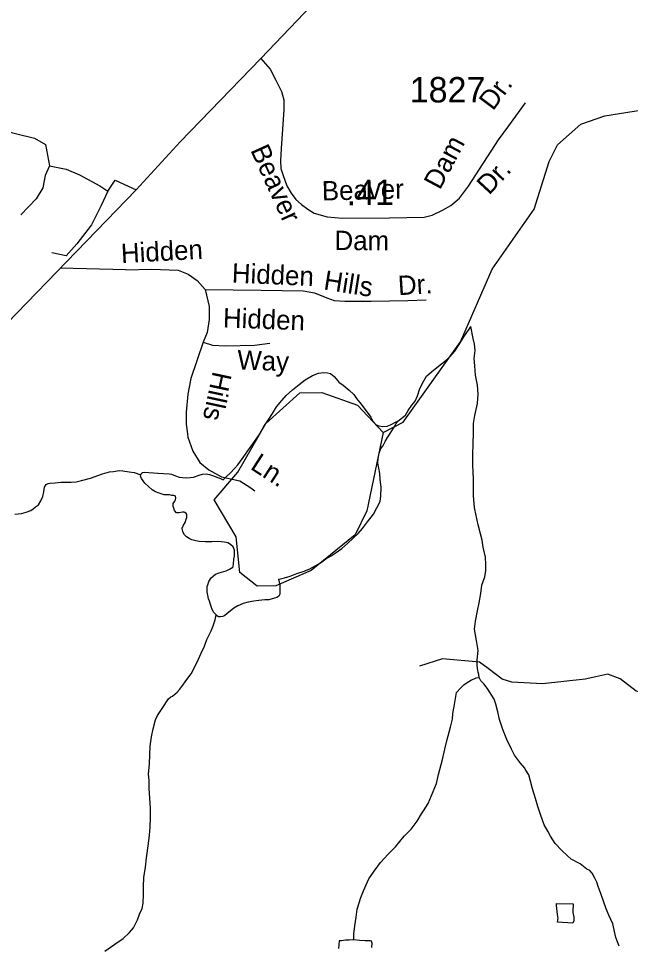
# Model space of a CAD drawing. Extents: x 2126262 to 2293712, y 749403 to 919119.
# Drawn here: x 2184249 to 2187256, y 811845 to 816398 of the extents above; entities that cross this region are included whole.
import ezdxf

# ---------------------------------------------------------------- set-up
doc = ezdxf.new("R2010")
doc.units = 0
for name, color, linetype in [('Exist Hydrographic Creek Single Shore', 7, 'Continuous'), ('Exist Hydrographic Misc Water Feature', 7, 'Continuous'), ('Exist Hydrographic Pond Under 1500 Sq Ft', 7, 'Continuous'), ('Exist Road Non-System Type 51', 7, 'Continuous'), ('Exist Road Non-System Type 51 Label', 7, 'Continuous'), ('Exist Road Primary US Attributed', 7, 'Continuous'), ('Exist Road Secondary Mileage Hundredths English Label', 7, 'Continuous'), ('Exist Road Secondary Type 51 Attributed', 7, 'Continuous'), ('Exist Road Secondary Type 51 Label', 7, 'Continuous'), ('Exist Road Secondary Type 51 Number Label', 7, 'Continuous')]:
    doc.layers.add(name, color=color, linetype=linetype)

msp = doc.modelspace()

# ---------------------------------------------------------------- linework, layer by layer
at = {"layer": 'Exist Hydrographic Creek Single Shore'}
msp.add_lwpolyline([(2186040.7, 814364.5), (2186139.7, 814414.9), (2186420.6, 814809.3), (2186576.7, 815167), (2186782.8, 815461.3), (2186855.8, 815695.9), (2186896.8, 815777.1), (2187012.6, 815879.7), (2187129.7, 815919.9), (2187345.6, 815954.8)], dxfattribs=at)
at = {"layer": 'Exist Hydrographic Misc Water Feature'}
for points in [[(2186112.5, 814420.1), (2186150.3, 814450.4), (2186164, 814472.5), (2186182.1, 814498.6), (2186197.9, 814518.7), (2186209.5, 814544.7), (2186221.2, 814580.8), (2186241.1, 814619), (2186253, 814641), (2186278.8, 814663.2), (2186296.9, 814677.3), (2186326.6, 814701.6), (2186350.4, 814719.7), (2186370.3, 814737.8), (2186392, 814763.9), (2186413.8, 814796.1), (2186437.6, 814834.2), (2186463.4, 814872.4), (2186471.4, 814884.4)], [(2186513, 813161.3), (2186511, 813175.2), (2186506.9, 813187.2), (2186504.8, 813207.2), (2186502.6, 813221.1), (2186502.6, 813247.1), (2186508.1, 813293.2), (2186499.9, 813343.1), (2186489.2, 813399), (2186495, 813437), (2186504.8, 813489.1), (2186512.6, 813527.1), (2186520.4, 813573.2), (2186526.1, 813615.2), (2186539.5, 813655.3), (2186545.6, 813687.3), (2186545.4, 813715.4), (2186543.2, 813751.3), (2186532.5, 813801.2), (2186526.3, 813835.2), (2186518.3, 813867.1), (2186507.9, 813911), (2186497.6, 813956.9), (2186489.2, 813996.8), (2186485.1, 814052.8), (2186484.5, 814102.8), (2186484.3, 814138.8), (2186481.8, 814202.7), (2186481.6, 814254.7), (2186483.1, 814310.7), (2186484.7, 814360.7), (2186484.5, 814408.6), (2186490.3, 814448.7), (2186503.8, 814506.8), (2186507.5, 814552.8), (2186503.4, 814596.7), (2186494.8, 814646.7), (2186490.7, 814692.7), (2186488.4, 814728.6), (2186492.1, 814766.6), (2186489.8, 814798.6), (2186483.5, 814826.5), (2186471.4, 814884.4)], [(2185254.8, 814132.3), (2185268.6, 814146.4), (2185288.6, 814164.5), (2185312.2, 814188.7), (2185326.4, 814204.8), (2185352, 814241), (2185375.8, 814275.1), (2185399.6, 814309.3), (2185427.3, 814347.4), (2185454.7, 814393.6), (2185478.5, 814429.8), (2185496.6, 814457.9), (2185516.3, 814490), (2185542.1, 814522.1), (2185563.8, 814546.3), (2185595.6, 814574.5), (2185627.6, 814600.7), (2185657.3, 814622.9), (2185693, 814645.2), (2185723.2, 814655.4), (2185749, 814659.5), (2185767, 814657.7), (2185781, 814653.8), (2185799, 814639.9), (2185809.3, 814628), (2185823.2, 814612.1), (2185843.3, 814596.2), (2185873.7, 814572.4), (2185895.8, 814550.6), (2185909.8, 814530.7), (2185930.1, 814504.9), (2185956.3, 814471), (2185980.5, 814439.2), (2185990.5, 814419.3), (2186006.7, 814401.4), (2186018.8, 814397.5), (2186036.9, 814393.6), (2186060.9, 814395.8), (2186076.7, 814401.9), (2186104.6, 814416.1), (2186112.5, 814420.1)], [(2185526.1, 813644.3), (2185530, 813644.3), (2185556, 813650.5), (2185584.1, 813658.7), (2185615.9, 813671), (2185651.8, 813683.2), (2185679.5, 813695.3), (2185709.6, 813711.6), (2185737.3, 813727.8), (2185759.2, 813743.9), (2185785.3, 813758.1), (2185809.1, 813774.2), (2185836.8, 813794.4), (2185866.9, 813820.6), (2185892.5, 813844.7), (2185918.4, 813868.9), (2185938.3, 813893.1), (2185964.1, 813925.3), (2185993.8, 813963.5), (2186025.4, 814025.7), (2186029.1, 814053.6), (2186030.7, 814093.6), (2186026.6, 814135.6), (2186024.4, 814163.6), (2186020.1, 814189.5), (2186014.1, 814213.5), (2186015.8, 814237.5), (2186021.5, 814263.5), (2186029.5, 814285.6), (2186039.3, 814297.7), (2186051.2, 814319.7), (2186061.1, 814339.8), (2186075, 814359.9), (2186090.8, 814386), (2186104.6, 814408.1), (2186112.5, 814420.1)], [(2184231, 813962.8), (2184263, 813967), (2184286.8, 813973.2), (2184308.9, 813981.2), (2184320.8, 813989.3), (2184332.9, 813999.4), (2184346.6, 814009.5), (2184358.5, 814029.5), (2184368.6, 814049.5), (2184372.3, 814073.6), (2184376.4, 814095.6), (2184384.2, 814109.6), (2184394, 814113.6), (2184402, 814115.7), (2184428, 814117.8), (2184458, 814120), (2184488.1, 814120.2), (2184508, 814120.3), (2184532, 814122.4), (2184558, 814128.6), (2184601.7, 814140.8), (2184661.8, 814161.1), (2184695.6, 814171.3), (2184715.5, 814173.4), (2184743.6, 814177.6), (2184761.5, 814175.7), (2184791.6, 814171.9), (2184817.6, 814168), (2184849.8, 814156.2)], [(2184849.8, 814156.2), (2184851.5, 814162.2), (2184857.6, 814168.3), (2184867.5, 814170.3), (2184933.5, 814164.6), (2184989.5, 814160.9)], [(2184989.5, 814160.9), (2184999.7, 814159.1), (2185019.8, 814151.2), (2185038.1, 814145.3), (2185054.1, 814143.4), (2185076.2, 814141.4), (2185108.6, 814145.4), (2185136.5, 814155.5), (2185152.5, 814159.6), (2185170.5, 814161.7), (2185186.5, 814157.8), (2185202.5, 814154), (2185240.9, 814138.2), (2185254.8, 814132.3)], [(2184990.3, 814059), (2184980.3, 814059), (2184964.3, 814058.9), (2184940.1, 814066.7), (2184922, 814072.7), (2184906, 814082.5), (2184869.7, 814116.3), (2184853.7, 814138.2), (2184847.8, 814150.2), (2184849.8, 814156.2)], [(2185219.3, 813468.3), (2185207.2, 813482.2), (2185199, 813500.2), (2185193.1, 813514), (2185186.7, 813536), (2185182.8, 813548), (2185178.7, 813565.9), (2185176.5, 813582), (2185176.5, 813596), (2185176.3, 813608), (2185178.3, 813616), (2185184.3, 813632), (2185196, 813650.1), (2185216.1, 813668.2), (2185234.1, 813674.3), (2185269.8, 813684.6), (2185285.8, 813692.7), (2185301.8, 813702.7), (2185303.8, 813706.7), (2185305.5, 813718.7), (2185307.5, 813742.8), (2185309.4, 813758.8), (2185309.2, 813786.8), (2185303, 813802.8), (2185291.1, 813814.7), (2185276.8, 813822.6), (2185260.8, 813826.4), (2185228.8, 813828.2), (2185198.8, 813828), (2185166.8, 813827.8), (2185136.9, 813829.6), (2185120.7, 813831.5), (2185100.8, 813837.3), (2185086.9, 813843.3), (2185074.8, 813851.2), (2185064.7, 813861.1), (2185056.5, 813877), (2185054.5, 813887), (2185052.6, 813895), (2185060.2, 813909), (2185068.2, 813923.1), (2185072.1, 813939.2), (2185076, 813947.2), (2185075.8, 813955.2), (2185075.8, 813961.2), (2185071.9, 813967.2), (2185065.8, 813971.2), (2185061.9, 813973.2), (2185053.9, 813973.2), (2185037.9, 813969), (2185031.7, 813969), (2185025.8, 813969), (2185015.3, 813981), (2185011.2, 813993), (2185009.2, 814001), (2185009.2, 814009), (2185008.8, 814015.1), (2185016.5, 814027.1), (2185020.6, 814033.1), (2185022.5, 814043.2), (2185020.2, 814049.1), (2185018.4, 814053.2), (2185012.2, 814055.1), (2185002.4, 814055.1), (2184990.3, 814059)], [(2185526.1, 813644.3), (2185532.3, 813614.4), (2185532.3, 813592.4), (2185532.7, 813570.4), (2185528.6, 813560.4), (2185518.5, 813554.3), (2185506.8, 813550.2), (2185478.7, 813542), (2185458.8, 813541.9), (2185428.9, 813539.7), (2185404.7, 813535.5), (2185376.8, 813531.3), (2185352.8, 813525.1), (2185327, 813513), (2185307.1, 813500.9), (2185289.3, 813486.8), (2185273.3, 813474.6), (2185261.4, 813464.6), (2185251.3, 813460.5), (2185241.3, 813458.4), (2185231.2, 813458.3), (2185223.2, 813464.3), (2185219.3, 813468.3)], [(2184997.9, 813065.4), (2185005.5, 813069.4), (2185027.6, 813089.5), (2185041.4, 813103.6), (2185055.5, 813123.6), (2185067.4, 813139.6), (2185081.3, 813157.5), (2185097.3, 813179.6), (2185113.1, 813209.6), (2185132.8, 813251.7), (2185146.5, 813279.8), (2185162.5, 813314), (2185174.2, 813348), (2185195.8, 813390.1), (2185205.8, 813414.2), (2185215.7, 813444.3), (2185219.3, 813468.3)], [(2185896, 811871.4), (2185895.8, 811899.4), (2185901.6, 811941.4), (2185907.3, 811983.4), (2185913, 812023.5), (2185930.5, 812079.6), (2185944.2, 812113.7), (2185970, 812171.8), (2185995.9, 812210), (2186027.5, 812252.2), (2186065, 812292.5), (2186100.9, 812328.7), (2186144.5, 812380.9), (2186178.4, 812415.2), (2186208.1, 812455.4), (2186229.8, 812491.5), (2186239.5, 812505.6), (2186261.2, 812541.7), (2186302.8, 812640), (2186312.3, 812684), (2186331.7, 812758.1), (2186343.6, 812808.2), (2186355.3, 812856.2), (2186370.7, 812916.3), (2186380.6, 812956.4), (2186382.4, 812984.4), (2186390, 813018.4), (2186395.7, 813058.5), (2186401.5, 813086.5), (2186421.6, 813110.7), (2186437.4, 813124.8), (2186449.2, 813132.8), (2186461.3, 813140.9), (2186475.1, 813149), (2186487, 813155.1), (2186497, 813159.2), (2186513, 813161.3)], [(2187199.7, 811840.4), (2187183.5, 811884.2), (2187169, 811950.1), (2187148.9, 811994), (2187136.6, 812023.9), (2187112.4, 812095.7), (2187097.8, 812133.6), (2187089.8, 812155.5), (2187081.6, 812175.4), (2187067.5, 812199.4), (2187055.4, 812213.3), (2187041.2, 812219.2), (2187009.2, 812244.9), (2186965.2, 812268.6), (2186947.1, 812284.5), (2186918.8, 812310.3), (2186886.6, 812346.1), (2186862.2, 812381.9), (2186850.1, 812405.8), (2186831.9, 812437.6), (2186813.6, 812487.5), (2186801.3, 812527.4), (2186789, 812567.3), (2186774.9, 812613.2), (2186764.6, 812651.1), (2186756.2, 812683.1), (2186738, 812711), (2186736.1, 812715), (2186715.8, 812740.7), (2186685.5, 812778.6), (2186671.3, 812808.5), (2186649, 812856.2), (2186628.9, 812906.1), (2186612.5, 812954), (2186604.3, 812991.9), (2186594, 813029.8), (2186585.8, 813053.8), (2186555.5, 813103.6), (2186537.2, 813127.5), (2186521, 813145.3), (2186513, 813161.3)], [(2184672.9, 811815.9), (2184722.5, 811850.2), (2184762.5, 811878.4), (2184794.3, 811908.6), (2184814, 811930.7), (2184833.8, 811970.8), (2184843.9, 811998.8), (2184855.6, 812026.9), (2184861.5, 812052.9), (2184863.4, 812094.9), (2184863, 812134.9), (2184864.8, 812178.9), (2184872.6, 812228.9), (2184878.3, 812274.9), (2184887.8, 812345), (2184891.5, 812387), (2184895.4, 812425), (2184897, 812473), (2184896.8, 812519), (2184894.5, 812568.9), (2184890.2, 812614.8), (2184890, 812652.9), (2184887.8, 812686.9), (2184891.5, 812734.9), (2184893.3, 812782.9), (2184895.2, 812822.9), (2184902.7, 812868.9), (2184910.5, 812908.9), (2184922.2, 812953), (2184932.3, 812975), (2184954, 813009.1), (2184985.8, 813055.3), (2184997.9, 813065.4)], [(2186973.4, 811954.7), (2186897.3, 811958.3), (2186901, 811976.3), (2186897.1, 811996.3), (2186894.8, 812026.2), (2186892.6, 812040.2), (2186892.6, 812046.2), (2186892.6, 812050.2), (2186974.6, 812048.7), (2186974.6, 812038.8), (2186972.7, 812020.8), (2186972.7, 812006.8), (2186977, 811982.8), (2186977, 811972.8), (2186977, 811964.8), (2186973.4, 811954.7)], [(2185896, 811871.4), (2185892.1, 811871.4), (2185874.1, 811871.2), (2185856, 811871.1), (2185836.1, 811867), (2185824, 811866.9), (2185822.4, 811846.9), (2185820.3, 811828.9)], [(2185984.4, 811834), (2185986.2, 811856), (2185984, 811866), (2185978, 811867.9), (2185952, 811867.8), (2185924.1, 811869.6), (2185896, 811871.4)]]:
    msp.add_lwpolyline(points, dxfattribs=at)
at = {"layer": 'Exist Hydrographic Pond Under 1500 Sq Ft'}
msp.add_lwpolyline([(2186040.7, 814364.5), (2185959.7, 813979), (2185902.7, 813862.1), (2185686.7, 813686.1), (2185512.6, 813611), (2185420.6, 813609.5), (2185336.7, 813676.9), (2185318.7, 813851.2), (2185209.6, 814033.9), (2185325.6, 814169.2), (2185464.7, 814409.2), (2185630.8, 814559.9), (2185738.6, 814560.9), (2185914.8, 814498.3), (2186040.7, 814364.5)], dxfattribs=at)
at = {"layer": 'Exist Road Non-System Type 51'}
for points in [[(2183871.3, 815933.2), (2183935.9, 815898.7), (2184152.2, 815852.6), (2184326.6, 815810.8), (2184381.7, 815779.3), (2184401.3, 815674.6)], [(2184401.3, 815674.6), (2184378.9, 815627.1), (2184367.8, 815565.7), (2184335, 815511.9), (2184259.6, 815433.7)], [(2184401.3, 815674.6), (2184482.9, 815658.5), (2184548.5, 815630.6), (2184647.5, 815576.1), (2184688, 815549.6)], [(2184688, 815549.6), (2184724.3, 815604.1), (2184826.3, 815557.2)], [(2184688, 815549.6), (2184654.5, 815479.8), (2184607.1, 815384.8), (2184534.5, 815291.3), (2184482.9, 815232.6), (2184413.1, 815246.9)], [(2184775.3, 815164.2), (2184453.1, 815171.6)], [(2184775.3, 815164.2), (2184902.8, 815166.4), (2185032.5, 815162), (2185083, 815142.2), (2185127, 815111.4), (2185166.5, 815067.4)], [(2185166.5, 815067.4), (2185186.3, 814983.8), (2185186.3, 814920.1), (2185175.3, 814856.3), (2185155.6, 814807.9)], [(2185166.5, 815067.4), (2185441.3, 815063), (2185647.9, 815060.8), (2185702.8, 815049.8), (2185764.3, 815025.6), (2185799.5, 815012.4), (2185852.3, 815010.2), (2185981.9, 815010.2), (2186162.1, 815012.4), (2186252.3, 815016.8)], [(2185155.6, 814807.9), (2185096.2, 814629.8), (2185080.8, 814552.8), (2185072, 814464.9), (2185072, 814405.5), (2185078.6, 814357.1), (2185080.8, 814341.7), (2185105, 814273.5), (2185140.2, 814216.4), (2185184.1, 814181.2), (2185245.7, 814146), (2185335.8, 814126.2), (2185390.7, 814093.2), (2185410.5, 814077.8)], [(2185155.6, 814807.9), (2185201.7, 814793.8), (2185265.4, 814789.4), (2185408.3, 814793.8), (2185483, 814802.6)], [(2187500.5, 813025.2), (2187351.2, 813076.8), (2187284.2, 813093.6), (2187206.1, 813155), (2187144.7, 813177.4), (2187086.1, 813163.4), (2187033.1, 813152.3), (2186823.8, 813129.9), (2186673.1, 813138.3), (2186625.6, 813152.3), (2186555.9, 813205.3), (2186514.4, 813236), (2186333, 813252.7), (2186219.1, 813216.5)]]:
    msp.add_lwpolyline(points, dxfattribs=at)
at = {"layer": 'Exist Road Primary US Attributed'}
for points in [[(2185438.9, 816202.5), (2185689.2, 816461.8), (2185825.5, 816609.4), (2185984.6, 816796.3), (2186086.8, 816919.2), (2186243.2, 817131.6)], [(2182674.5, 812949.4), (2182962.2, 813399.7), (2183098.6, 813609.3), (2183288, 813886.4), (2183352.6, 813982.6), (2183512, 814170.5), (2183661.3, 814340.9), (2183700.5, 814386.9), (2184142.6, 814850.6), (2184826.3, 815557.2), (2185042.9, 815792.2), (2185438.9, 816202.5)]]:
    msp.add_lwpolyline(points, dxfattribs=at)
at = {"layer": 'Exist Road Secondary Type 51 Attributed'}
msp.add_lwpolyline([(2185438.9, 816202.5), (2185484.8, 816149.4), (2185512.7, 816095.7), (2185541.6, 816038.9), (2185552.9, 815998.7), (2185552.9, 815950.1), (2185539.5, 815760.2), (2185536.4, 815698.2), (2185538.5, 815661), (2185549.8, 815627), (2185567.4, 815576.4), (2185588.1, 815540.7), (2185610.8, 815509.8), (2185638.6, 815483.9), (2185669.6, 815461.2), (2185701.6, 815441.6), (2185764.6, 815424.1), (2185841, 815417.9), (2186072.3, 815419.4), (2186241.7, 815422.5), (2186281.9, 815431.8), (2186332.5, 815456.6), (2186372.8, 815479.3), (2186415.1, 815515.4), (2186460.6, 815575.3), (2186607.2, 815802), (2186658.8, 815870.6), (2186740.4, 815984.2)], dxfattribs=at)

# ---------------------------------------------------------------- texts
at = {"layer": 'Exist Road Non-System Type 51 Label'}
for s, rotation, p in [('Dr.', 53.1574, (2186580, 815941.1)), ('Dam', 61.9511, (2186319.3, 815552.3)), ('Beaver', 1.4703, (2185740.5, 815503.8)), ('Hidden', 3.0088, (2184754.4, 815196.6)), ('Hidden', 357.5723, (2185295.7, 815100.9)), ('Hills', 351.0186, (2185744.3, 815067.8)), ('Dr.', 3.507, (2186116.1, 815038.6)), ('Hidden', 357.9033, (2185252, 814880.9)), ('Way', 357.9033, (2185322.3, 814674.5)), ('Hills', 257.9236, (2185204.3, 814668.5)), ('Ln.', 327.1099, (2185382.9, 814187.9))]:
    msp.add_text(s, height=95, rotation=rotation, dxfattribs=at).set_placement(p)
at = {"layer": 'Exist Road Secondary Mileage Hundredths English Label'}
msp.add_text('.41', height=125, rotation=0.3837, dxfattribs=at).set_placement((2185860.8, 815480.5))
at = {"layer": 'Exist Road Secondary Type 51 Label'}
for s, rotation, p in [('Beaver', 294.4241, (2185386.7, 815751.9)), ('Dr.', 47.2026, (2186561.1, 815527.4)), ('Dam', 359.7024, (2185801.4, 815260.8))]:
    msp.add_text(s, height=95, rotation=rotation, dxfattribs=at).set_placement(p)
at = {"layer": 'Exist Road Secondary Type 51 Number Label'}
msp.add_text('1827', height=125, dxfattribs=at).set_placement((2186171.1, 815985.7))

doc.saveas('drawing.dxf')
